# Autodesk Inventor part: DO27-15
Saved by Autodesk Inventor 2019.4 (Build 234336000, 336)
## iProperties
Created: 2020-03
Part Number: DO27-15
Material: Generic
Document SubType Name: Modeling
Designer: Administrator
Density: 1 g/cm^3
Appearance: Default
Title: DO27-15
Author: Administrator
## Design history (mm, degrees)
feature "Body2"
body "Solid1"
